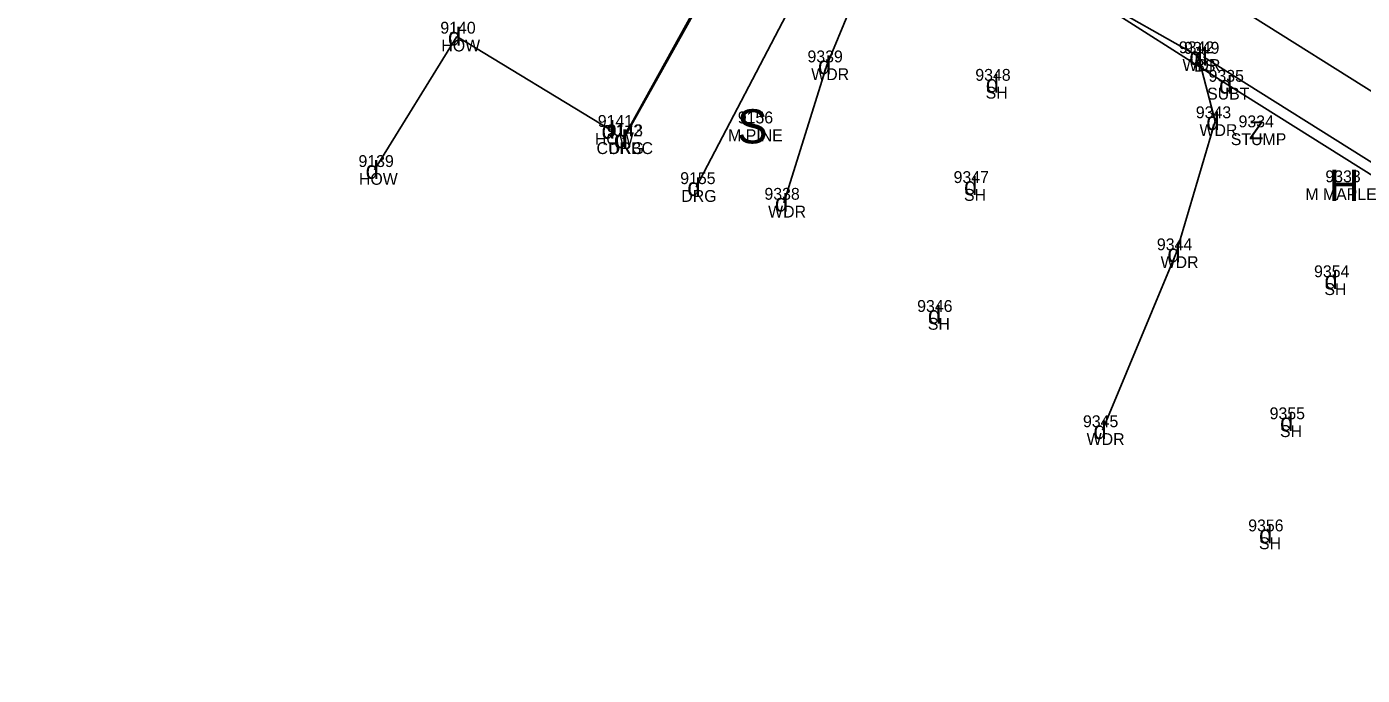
# Model space of a CAD drawing. Extents: x 69415 to 80913, y 7576 to 15059.
# Drawn here: x 78062.8 to 78287.8, y 12705.2 to 12814.5 of the extents above; entities that cross this region are included whole.
import ezdxf

# ---------------------------------------------------------------- set-up
doc = ezdxf.new("R2010")
doc.units = 0
for name, color, linetype in [('Level 11', 7, 'Continuous'), ('Level 13', 7, 'Continuous'), ('Level 14', 7, 'Continuous'), ('Level 15', 7, 'Continuous'), ('Level 46', 7, 'Continuous'), ('Level 47', 7, 'Continuous'), ('Level 48', 7, 'Continuous')]:
    doc.layers.add(name, color=color, linetype=linetype)

msp = doc.modelspace()

# ---------------------------------------------------------------- linework, layer by layer
at = {"layer": 'Level 11'}
for p, q in [((78163.22, 12795.57), (78178.86, 12823.86)), ((78163.36, 12795.57), (78179.01, 12823.59)), ((78192.05, 12818.94), (78175.59, 12787.51)), ((78266.82, 12817.81), (78309.38, 12791.08))]:
    msp.add_line(p, q, dxfattribs=at)
at = {"layer": 'Level 13'}
for p, q in [((78121.39, 12790.39), (78135.26, 12812.87)), ((78135.26, 12812.87), (78161.14, 12797.15))]:
    msp.add_line(p, q, dxfattribs=at)
at = {"layer": 'Level 14'}
for p, q in [((78197.6, 12808.03), (78209.96, 12838.16)), ((78240.67, 12820.62), (78260.17, 12809.57)), ((78260.17, 12809.57), (78263.03, 12798.61)), ((78190.35, 12784.87), (78197.6, 12808.03)), ((78263.03, 12798.61), (78256.47, 12776.35)), ((78256.47, 12776.35), (78244.02, 12746.53))]:
    msp.add_line(p, q, dxfattribs=at)
at = {"layer": 'Level 15'}
for p, q in [((77872.12, 13054.89), (78265.18, 12804.76)), ((78265.18, 12804.76), (78754.05, 12497.03))]:
    msp.add_line(p, q, dxfattribs=at)
at = {"layer": 'Level 48'}
msp.add_line((78261.05, 12809.48), (78303.54, 12782.78), dxfattribs=at)

# ---------------------------------------------------------------- texts
at = {"layer": 'Level 14'}
for s, height, p in [('S', 5.75, (78182.48, 12794.87)), ('Z', 3, (78268.73, 12795.58)), ('H', 5.3, (78282.21, 12785.17))]:
    msp.add_text(s, height=height, dxfattribs=at).set_placement(p)
at = {"layer": 'Level 46'}
for s, p in [('9140', (78132.48, 12813.37)), ('HOW', (78132.65, 12810.37)), ('9342', (78256.91, 12810.07)), ('9349', (78257.79, 12809.98)), ('9339', (78194.34, 12808.53)), ('WDR', (78257.53, 12807.07)), ('BS', (78259.49, 12806.98)), ('WDR', (78194.97, 12805.53)), ('9348', (78222.62, 12805.42)), ('9335', (78261.92, 12805.26)), ('SH', (78224.36, 12802.42)), ('SUBT', (78261.67, 12802.26)), ('9141', (78159.01, 12797.65)), ('9156', (78182.6, 12798.24)), ('9343', (78259.77, 12799.11)), ('9334', (78266.97, 12797.58)), ('9142', (78160.53, 12796.07)), ('9143', (78160.67, 12796.07)), ('WDR', (78260.39, 12796.11)), ('HOW', (78158.52, 12794.65)), ('CURBC', (78158.8, 12793.07)), ('DRG', (78160.85, 12793.07)), ('M.PINE', (78180.96, 12795.24)), ('STUMP', (78265.66, 12794.58)), ('9139', (78118.69, 12790.89)), ('HOW', (78118.77, 12787.89)), ('9155', (78172.9, 12788.01)), ('9347', (78218.96, 12788.19)), ('9333', (78281.6, 12788.32)), ('DRG', (78173.08, 12785.01)), ('9338', (78187.09, 12785.37)), ('SH', (78220.71, 12785.19)), ('M MAPLE', (78278.21, 12785.32)), ('WDR', (78187.71, 12782.37)), ('9344', (78253.21, 12776.85)), ('WDR', (78253.84, 12773.85)), ('9354', (78279.69, 12772.31)), ('SH', (78281.43, 12769.31)), ('9346', (78212.82, 12766.46)), ('SH', (78214.62, 12763.46)), ('9355', (78272.21, 12748.37)), ('9345', (78240.76, 12747.03)), ('WDR', (78241.38, 12744.03)), ('SH', (78273.95, 12745.37)), ('9356', (78268.6, 12729.47)), ('SH', (78270.41, 12726.47))]:
    msp.add_text(s, height=2, dxfattribs=at).set_placement(p)
at = {"layer": 'Level 47'}
for p in [(78133.76, 12811.37), (78258.67, 12808.07), (78259.55, 12807.98), (78196.1, 12806.53), (78224.38, 12803.42), (78263.68, 12803.26), (78261.53, 12797.11), (78159.64, 12795.65), (78161.72, 12794.07), (78161.86, 12794.07), (78119.89, 12788.89), (78174.09, 12786.01), (78220.72, 12786.19), (78188.85, 12783.37), (78254.97, 12774.85), (78281.45, 12770.31), (78214.63, 12764.46), (78242.52, 12745.03), (78273.96, 12746.37), (78270.42, 12727.47)]:
    msp.add_text('d', height=3, dxfattribs=at).set_placement(p)

doc.saveas('drawing.dxf')
